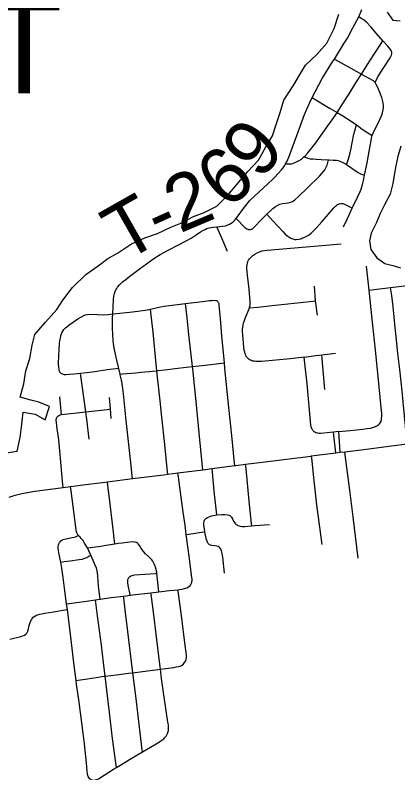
# Model space of a CAD drawing. Extents: x 0 to 34, y -5.4 to 22.
# Drawn here: x 2.686 to 3.075, y 18.856 to 19.626 of the extents above; entities that cross this region are included whole.
import ezdxf

# ---------------------------------------------------------------- set-up
doc = ezdxf.new("R2010")
doc.units = 0
for name, color, linetype in [('GM_X_Corporation_Text', 7, 'Continuous'), ('GM_X_Major_Lake', 7, 'Continuous'), ('GM_X_Major_River', 7, 'Continuous'), ('GM_X_State_Route', 7, 'Continuous'), ('GM_X_Township_Road', 7, 'Continuous'), ('GM_X_Township_Road_Text', 7, 'Continuous')]:
    doc.layers.add(name, color=color, linetype=linetype)

msp = doc.modelspace()

# ---------------------------------------------------------------- linework, layer by layer
at = {"layer": 'GM_X_Major_Lake'}
msp.add_lwpolyline([(2.67653, 19.18094), (2.68793, 19.18266), (2.69079, 19.19666), (2.69252, 19.2103), (2.69384, 19.22242), (2.70611, 19.22053), (2.71626, 19.21474), (2.72083, 19.22807), (2.70997, 19.23262), (2.7016, 19.23445), (2.69104, 19.23765), (2.69466, 19.25126), (2.69675, 19.26451), (2.70073, 19.27697), (2.70321, 19.2906), (2.70565, 19.30119), (2.71645, 19.31392), (2.72802, 19.32665), (2.73423, 19.33642), (2.7439, 19.34917), (2.75774, 19.36224), (2.77, 19.37116), (2.77997, 19.37859), (2.7899, 19.38413), (2.80406, 19.3934), (2.81742, 19.39964), (2.83038, 19.40399), (2.84412, 19.41061), (2.85403, 19.41463), (2.86702, 19.42126), (2.87769, 19.42527), (2.89067, 19.4319), (2.90184, 19.44311), (2.9111, 19.45397), (2.92228, 19.46708), (2.93307, 19.47868), (2.94009, 19.49147), (2.94709, 19.50313), (2.95066, 19.5137), (2.95503, 19.52692), (2.95863, 19.53938), (2.9691, 19.55516), (2.97456, 19.56494), (2.98078, 19.5751), (2.99231, 19.58592), (3.00234, 19.59753), (3.00976, 19.61222), (3.01453, 19.62695)], dxfattribs=at)
at = {"layer": 'GM_X_Major_River'}
for points in [[(3.06383, 19.62883), (3.06939, 19.62077), (3.07696, 19.62028)], [(3.07767, 19.49273), (3.07447, 19.48216), (3.07244, 19.4727), (3.07078, 19.46324), (3.06951, 19.45491), (3.06669, 19.44394), (3.06122, 19.43302), (3.05654, 19.42437), (3.05299, 19.41531), (3.04752, 19.40439), (3.04588, 19.39644), (3.04727, 19.38769), (3.0532, 19.37925), (3.06145, 19.37343), (3.06937, 19.3714), (3.07729, 19.36901)]]:
    msp.add_lwpolyline(points, dxfattribs=at)
at = {"layer": 'GM_X_State_Route'}
msp.add_lwpolyline([(2.67957, 19.13608), (2.6858, 19.13813), (2.69242, 19.13973), (2.70584, 19.14214), (2.72147, 19.14416), (2.73458, 19.14588), (2.74216, 19.14687), (2.75212, 19.14818), (2.77961, 19.15162), (2.80515, 19.15482), (2.83653, 19.15875), (2.84098, 19.15931), (2.85118, 19.16062), (2.87656, 19.16387), (2.88581, 19.16506), (2.90901, 19.16804), (2.90987, 19.16814), (2.91997, 19.16941), (2.93392, 19.17116), (2.98629, 19.17784), (2.98691, 19.17792), (3.01146, 19.18105), (3.01602, 19.18164), (3.02083, 19.18222), (3.03992, 19.18463), (3.06828, 19.18825), (3.08399, 19.19021)], dxfattribs=at)
at = {"layer": 'GM_X_Township_Road'}
for p, q in [((2.73292, 19.2199), (2.73107, 19.23797)), ((3.01146, 19.18105), (3.0091, 19.20211)), ((3.01602, 19.18164), (3.01449, 19.20265)), ((2.82378, 19.0389), (2.83189, 19.0398)), ((2.76734, 19.03165), (2.77203, 19.03232)), ((2.73884, 19.02188), (2.73812, 19.02761))]:
    msp.add_line(p, q, dxfattribs=at)
for points in [[(2.94838, 19.45993), (2.94976, 19.46121), (2.95316, 19.46492), (2.95632, 19.46857), (2.95796, 19.47067), (2.95936, 19.47266), (2.96062, 19.47474), (2.96204, 19.47758), (2.96459, 19.48331), (2.97703, 19.51768), (2.97994, 19.5249), (2.98223, 19.53034), (2.98505, 19.53725), (2.98745, 19.54216), (2.9908, 19.54868), (2.99785, 19.56151), (3.00831, 19.57846), (3.0101, 19.58132), (3.02015, 19.59737), (3.02336, 19.60271), (3.02898, 19.61296), (3.0349, 19.62432), (3.03806, 19.6317)], [(3.06854, 19.58675), (3.06855, 19.58742), (3.0685, 19.58827), (3.06832, 19.58916), (3.06793, 19.59011), (3.06724, 19.59115), (3.06436, 19.5945), (3.05947, 19.59998), (3.05273, 19.60752), (3.04705, 19.61412), (3.04261, 19.61872), (3.04025, 19.62075), (3.03749, 19.6227), (3.0349, 19.62432)], [(2.96062, 19.47474), (2.96252, 19.47469), (2.9647, 19.47474), (2.96683, 19.47497), (2.9685, 19.47543), (2.97155, 19.47682), (2.97422, 19.47824), (2.97657, 19.47974), (2.97923, 19.48187), (2.98035, 19.48287), (2.98322, 19.48585), (2.99023, 19.49466), (3.00181, 19.51095), (3.01139, 19.52442), (3.01302, 19.52705), (3.01937, 19.5373), (3.02501, 19.54605), (3.03196, 19.55727), (3.03761, 19.56598), (3.04628, 19.57937), (3.05755, 19.59698), (3.05947, 19.59998)], [(3.05168, 19.55737), (3.05251, 19.55957), (3.05405, 19.56266), (3.05586, 19.56581), (3.06626, 19.58139), (3.0676, 19.58383), (3.06818, 19.58525), (3.06854, 19.58675)], [(3.0101, 19.58132), (3.02669, 19.5721), (3.03761, 19.56598), (3.04079, 19.56419), (3.04942, 19.55937), (3.05065, 19.55847), (3.05168, 19.55737)], [(3.01932, 19.41068), (3.02333, 19.41926), (3.02826, 19.42982), (3.03349, 19.44085), (3.03632, 19.44683), (3.0373, 19.44914), (3.03819, 19.45154), (3.03918, 19.45507), (3.03978, 19.45775), (3.04086, 19.46333), (3.04355, 19.47596), (3.04488, 19.48364), (3.04752, 19.49855), (3.04796, 19.50103), (3.04862, 19.50363), (3.04945, 19.50608), (3.05061, 19.5084), (3.05434, 19.51561), (3.05807, 19.52378), (3.05903, 19.52675), (3.05974, 19.52977), (3.05999, 19.53215), (3.05993, 19.53415), (3.0596, 19.53698), (3.05909, 19.53948), (3.05819, 19.54219), (3.05413, 19.55236), (3.05271, 19.55545), (3.05168, 19.55737)], [(2.98745, 19.54216), (2.98967, 19.54081), (3.00587, 19.5312), (3.01302, 19.52705), (3.01886, 19.52368), (3.02714, 19.51835), (3.03253, 19.51444), (3.03449, 19.51301), (3.03693, 19.51125), (3.04151, 19.508), (3.04578, 19.50524), (3.04862, 19.50363)], [(3.02251, 19.47417), (3.02313, 19.476), (3.02452, 19.47992), (3.02525, 19.48215), (3.02627, 19.48602), (3.02683, 19.489), (3.02814, 19.49633), (3.03006, 19.50484), (3.03096, 19.50846), (3.03193, 19.51214), (3.03253, 19.51444)], [(2.94136, 19.42352), (2.94751, 19.4295), (2.95028, 19.43155), (2.95269, 19.43288), (2.9548, 19.43373), (2.95746, 19.43434), (2.96331, 19.4353), (2.96553, 19.43582), (2.96741, 19.43657), (2.96994, 19.43832), (2.97374, 19.44158), (2.98255, 19.44997), (2.99509, 19.46241), (2.99901, 19.46688), (3.0004, 19.46875), (3.00125, 19.47014), (3.00214, 19.472), (3.00277, 19.47355), (3.00352, 19.47624), (3.00413, 19.479)], [(2.97923, 19.48187), (2.98119, 19.48116), (2.98317, 19.48044), (2.98552, 19.47998), (2.98853, 19.4798), (2.99177, 19.47961), (2.99658, 19.47937), (3.00413, 19.479), (3.00488, 19.47896), (3.00886, 19.47872), (3.01064, 19.47872), (3.01243, 19.47858), (3.01389, 19.4783), (3.01563, 19.47769), (3.01931, 19.47591), (3.02251, 19.47417), (3.02776, 19.47053), (3.03432, 19.46598), (3.03682, 19.46457), (3.03884, 19.46382), (3.04086, 19.46333)], [(2.91047, 19.41932), (2.91876, 19.43086), (2.92398, 19.43712), (2.92924, 19.44247), (2.94219, 19.45418), (2.94838, 19.45993)], [(2.94136, 19.42352), (2.94746, 19.41691), (2.95759, 19.40599), (2.96029, 19.40349), (2.96271, 19.40147), (2.96579, 19.39938), (2.96808, 19.39843), (2.96952, 19.39804), (2.97121, 19.39784), (2.97405, 19.39814), (2.97589, 19.39867), (2.97723, 19.3992), (2.97999, 19.40036), (2.98264, 19.40162), (2.98442, 19.40265), (2.9865, 19.40442), (2.99181, 19.40987), (2.99731, 19.41581), (3.00389, 19.42346), (3.00971, 19.4302), (3.01122, 19.43174), (3.01214, 19.43261), (3.01334, 19.43355), (3.01434, 19.43398), (3.01547, 19.43431), (3.01673, 19.43452), (3.01859, 19.43439), (3.01989, 19.43403), (3.02094, 19.4336), (3.02584, 19.43107), (3.02826, 19.42982)], [(2.91047, 19.41932), (2.91913, 19.41007), (2.92017, 19.4093), (2.92122, 19.40874), (2.9221, 19.40841), (2.92301, 19.40823), (2.92394, 19.40816), (2.92486, 19.40824), (2.92585, 19.40852), (2.9266, 19.40884), (2.92761, 19.40949), (2.9286, 19.41031), (2.93658, 19.41858), (2.94136, 19.42352)], [(2.80515, 19.15482), (2.80484, 19.15739), (2.80318, 19.1714), (2.79863, 19.21392), (2.79596, 19.24119), (2.79494, 19.24904), (2.79379, 19.25507), (2.79253, 19.26045), (2.79238, 19.26108), (2.79105, 19.26677), (2.78908, 19.27517), (2.78737, 19.28287), (2.78616, 19.28953), (2.78542, 19.29537), (2.78496, 19.30137), (2.78476, 19.30827), (2.78478, 19.31811), (2.78495, 19.32222), (2.78524, 19.32929), (2.78572, 19.33698), (2.78614, 19.34022), (2.78663, 19.34295), (2.78736, 19.34496), (2.78814, 19.34672), (2.78893, 19.34813), (2.78981, 19.34939), (2.79179, 19.35184), (2.79484, 19.35476), (2.79809, 19.35742), (2.80237, 19.36079), (2.81175, 19.36761), (2.82668, 19.37848), (2.83299, 19.38256), (2.84191, 19.38734), (2.85122, 19.39203), (2.85968, 19.39642), (2.86472, 19.39934), (2.86977, 19.40275), (2.87403, 19.40562), (2.87652, 19.40714), (2.87872, 19.40823), (2.88066, 19.40908), (2.88291, 19.40976), (2.88693, 19.41043), (2.89073, 19.41084), (2.89666, 19.41147), (2.89946, 19.41195), (2.90184, 19.41275), (2.90356, 19.4136), (2.90525, 19.41455), (2.90717, 19.41575), (2.90877, 19.41732), (2.91047, 19.41932)], [(2.90149, 19.38586), (2.89944, 19.39061), (2.89604, 19.39851), (2.89211, 19.40762), (2.89073, 19.41084)], [(3.01449, 19.20265), (3.0091, 19.20211), (2.99609, 19.20089), (2.99463, 19.20088), (2.99343, 19.20101), (2.9925, 19.20119), (2.99143, 19.20154), (2.99023, 19.20212), (2.98958, 19.20257), (2.9887, 19.20332), (2.98809, 19.20406), (2.98763, 19.20481), (2.98706, 19.20588), (2.98665, 19.20743), (2.98631, 19.20919), (2.98238, 19.25127), (2.9804, 19.269), (2.97935, 19.27848), (2.96542, 19.27676), (2.93608, 19.27403), (2.93359, 19.27385), (2.93035, 19.27387), (2.92861, 19.27409), (2.92709, 19.27437), (2.92582, 19.27479), (2.92458, 19.27535), (2.92359, 19.27593), (2.92289, 19.27649), (2.92217, 19.27716), (2.92147, 19.27795), (2.92065, 19.27901), (2.92006, 19.28024), (2.91951, 19.28162), (2.91899, 19.28335), (2.91856, 19.28545), (2.91815, 19.2884), (2.91687, 19.30459), (2.9169, 19.30665), (2.91704, 19.30843), (2.91741, 19.31076), (2.91789, 19.31283), (2.91875, 19.31543), (2.91993, 19.3186), (2.92346, 19.32739), (2.92379, 19.32841), (2.92403, 19.32915), (2.92447, 19.33092), (2.92467, 19.33269), (2.92466, 19.33503), (2.92352, 19.34754), (2.92191, 19.36174), (2.92151, 19.36563), (2.92132, 19.36824), (2.92132, 19.37003), (2.92151, 19.3725), (2.92184, 19.37401), (2.92231, 19.37553), (2.92293, 19.37677), (2.92404, 19.37831), (2.92525, 19.37971), (2.92733, 19.38155), (2.92944, 19.38309), (2.93169, 19.38445), (2.93401, 19.38554), (2.93662, 19.3863), (2.9418, 19.38713), (2.99743, 19.39188), (3.01687, 19.39368)], [(3.01449, 19.20265), (3.02627, 19.20382), (3.03912, 19.20511), (3.04333, 19.20568), (3.04727, 19.2063), (3.04997, 19.20706), (3.05205, 19.20787), (3.05332, 19.20851), (3.0543, 19.20918), (3.05528, 19.21), (3.05596, 19.2107), (3.05673, 19.21167), (3.05719, 19.21257), (3.05762, 19.21366), (3.0579, 19.21473), (3.05812, 19.21619), (3.05823, 19.21758), (3.05821, 19.2209), (3.05778, 19.22706), (3.05564, 19.24829), (3.05213, 19.2823), (3.04854, 19.31702), (3.04549, 19.34634), (3.04282, 19.37092)], [(2.99283, 19.32095), (2.9911, 19.33548), (2.98984, 19.35046)], [(3.04549, 19.34634), (3.05041, 19.34695), (3.06731, 19.34905), (3.07819, 19.35038), (3.09072, 19.35179), (3.09471, 19.35212), (3.09605, 19.35207), (3.0975, 19.35191), (3.09846, 19.35172), (3.09948, 19.35131), (3.10025, 19.35087)], [(3.08399, 19.19021), (3.08364, 19.19409), (3.08077, 19.22573), (3.07914, 19.24367), (3.07812, 19.25333), (3.07679, 19.26592), (3.07473, 19.28202), (3.07307, 19.29926), (3.07199, 19.30802), (3.0697, 19.32982), (3.06839, 19.34086), (3.06731, 19.34905)], [(2.78495, 19.32222), (2.78862, 19.32261), (2.80204, 19.32404), (2.81089, 19.32499), (2.81509, 19.32558), (2.81806, 19.32609), (2.82321, 19.32722), (2.83357, 19.32949), (2.83722, 19.33014), (2.84273, 19.33095), (2.85901, 19.33285), (2.87872, 19.33533), (2.88309, 19.33581), (2.88604, 19.33606), (2.88795, 19.3361), (2.88943, 19.33599), (2.89035, 19.33579), (2.89113, 19.33543)], [(2.87656, 19.16387), (2.87627, 19.16676), (2.87274, 19.20157), (2.86969, 19.23326), (2.86621, 19.26657), (2.86598, 19.26872), (2.86273, 19.29837), (2.86023, 19.3215), (2.85901, 19.33285)], [(2.90901, 19.16804), (2.90875, 19.1706), (2.90586, 19.19876), (2.90306, 19.22722), (2.89892, 19.26679), (2.89842, 19.27241), (2.89594, 19.30016), (2.89447, 19.31777), (2.89311, 19.33125), (2.89292, 19.33246), (2.89275, 19.33306), (2.89255, 19.33356), (2.89213, 19.33433), (2.89165, 19.33497), (2.89113, 19.33543)], [(2.92379, 19.32841), (2.93251, 19.32929), (2.94675, 19.33073), (2.98519, 19.33485), (2.9911, 19.33548)], [(2.84098, 19.15931), (2.84071, 19.16179), (2.83778, 19.18958), (2.83483, 19.21733), (2.83313, 19.23399), (2.83181, 19.24604), (2.83052, 19.25784), (2.8297, 19.26453), (2.8293, 19.26774), (2.82588, 19.30364), (2.82393, 19.32087), (2.82321, 19.32722)], [(2.79105, 19.26677), (2.78847, 19.26644), (2.77928, 19.26527), (2.76688, 19.26355), (2.75877, 19.26245), (2.75227, 19.26183), (2.74551, 19.26119), (2.74108, 19.26083), (2.73725, 19.2605), (2.73595, 19.2605), (2.73487, 19.26067), (2.7341, 19.26091), (2.73318, 19.26131), (2.73238, 19.26185), (2.73173, 19.26247), (2.73129, 19.26312), (2.73094, 19.26398), (2.73061, 19.26493), (2.73036, 19.26603), (2.73003, 19.26831), (2.72985, 19.27123), (2.73008, 19.28013), (2.731, 19.29214), (2.7313, 19.29502), (2.73171, 19.29767), (2.73233, 19.30042), (2.73332, 19.3031), (2.73417, 19.3046), (2.73535, 19.30638), (2.73694, 19.30808), (2.7418, 19.31195), (2.74947, 19.31721), (2.75541, 19.32057), (2.75708, 19.32124), (2.75928, 19.32179), (2.76139, 19.32198), (2.76913, 19.32161), (2.77583, 19.32131), (2.78069, 19.32162), (2.78495, 19.32222)], [(2.97935, 19.27848), (2.99139, 19.28), (2.99732, 19.28067), (3.0111, 19.28222)], [(3.00059, 19.24548), (2.99771, 19.27648), (2.99732, 19.28067)], [(2.79238, 19.26108), (2.79442, 19.26126), (2.80388, 19.26209), (2.80816, 19.26248), (2.81349, 19.26296), (2.81752, 19.26332), (2.82213, 19.26377), (2.82533, 19.26407), (2.8297, 19.26453), (2.83076, 19.26465), (2.83792, 19.26549), (2.84846, 19.26672), (2.85943, 19.26798), (2.86598, 19.26872), (2.87893, 19.2702), (2.89842, 19.27241)], [(2.76109, 19.19506), (2.7587, 19.21545), (2.75769, 19.22276), (2.75634, 19.2325), (2.7526, 19.2595), (2.75227, 19.26183)], [(2.78347, 19.21606), (2.78261, 19.22564), (2.78158, 19.2373)], [(2.73458, 19.14588), (2.73434, 19.14859), (2.73134, 19.18297), (2.73006, 19.19435), (2.72815, 19.20808), (2.72767, 19.21218), (2.72751, 19.21393), (2.7276, 19.21496), (2.72777, 19.21591), (2.72795, 19.21646), (2.72829, 19.21708), (2.72859, 19.21759), (2.72921, 19.21828), (2.72989, 19.21879), (2.73082, 19.21931), (2.73164, 19.21958), (2.73292, 19.2199), (2.75769, 19.22276), (2.77928, 19.22526), (2.78261, 19.22564)], [(2.99787, 19.08798), (2.9923, 19.12819), (2.98918, 19.15575), (2.98742, 19.17301), (2.98691, 19.17792)], [(3.03416, 19.07394), (3.02913, 19.11593), (3.02589, 19.14303), (3.02125, 19.17898), (3.02083, 19.18222)], [(2.92625, 19.10682), (2.92602, 19.10911), (2.92371, 19.1321), (2.92043, 19.16485), (2.91997, 19.16941)], [(2.89061, 19.1179), (2.88814, 19.14221), (2.88618, 19.16144), (2.88581, 19.16506)], [(2.86318, 19.04568), (2.86387, 19.04648), (2.86433, 19.04721), (2.86472, 19.04807), (2.86516, 19.04926), (2.86538, 19.05021), (2.8655, 19.05119), (2.86547, 19.05265), (2.86538, 19.05419), (2.86511, 19.05685), (2.86258, 19.07592), (2.85966, 19.0981), (2.85842, 19.1074), (2.85664, 19.1207), (2.85177, 19.15636), (2.85118, 19.16062)], [(2.77203, 19.03232), (2.77061, 19.04538), (2.77012, 19.05095), (2.76971, 19.05561), (2.76929, 19.0593), (2.76876, 19.0624), (2.76827, 19.06403), (2.76721, 19.06662), (2.76611, 19.06926), (2.76264, 19.07699), (2.76062, 19.0815), (2.75915, 19.08462), (2.75636, 19.08936), (2.75445, 19.09239), (2.75299, 19.09415), (2.75169, 19.09547), (2.74986, 19.09712), (2.74905, 19.09827), (2.7483, 19.09988), (2.74803, 19.10084), (2.74767, 19.10283), (2.74526, 19.12133), (2.74268, 19.1425), (2.74216, 19.14687)], [(2.78704, 19.08861), (2.78637, 19.09413), (2.78527, 19.10336), (2.78155, 19.13472), (2.78005, 19.14775), (2.77961, 19.15162)], [(2.87858, 19.10077), (2.87806, 19.10397), (2.87764, 19.10753), (2.8776, 19.1097), (2.87786, 19.11165), (2.87812, 19.11258), (2.87866, 19.11342), (2.87963, 19.11431), (2.88109, 19.11524), (2.88287, 19.11604), (2.88543, 19.11688), (2.89061, 19.1179)], [(2.89061, 19.1179), (2.8958, 19.11826), (2.89894, 19.11826), (2.9016, 19.11804), (2.90315, 19.11769), (2.90397, 19.11734), (2.90465, 19.11685), (2.90576, 19.11565), (2.90665, 19.11414), (2.90776, 19.11173), (2.9086, 19.11021), (2.90926, 19.10932), (2.91033, 19.1083), (2.91121, 19.10773), (2.91219, 19.1072), (2.91339, 19.10671), (2.91441, 19.10649), (2.91644, 19.10627), (2.91905, 19.10632), (2.92625, 19.10682), (2.92947, 19.10709), (2.94429, 19.10827)], [(2.85966, 19.0981), (2.86222, 19.0985), (2.87501, 19.10028), (2.87858, 19.10077)], [(2.89839, 19.05876), (2.89669, 19.07508), (2.89612, 19.0787), (2.89542, 19.08152), (2.89479, 19.08325), (2.89419, 19.08411), (2.89366, 19.08464), (2.89309, 19.08518), (2.89197, 19.08587), (2.8907, 19.08634), (2.88874, 19.08667), (2.88549, 19.087), (2.88426, 19.08726), (2.88336, 19.08766), (2.8826, 19.08823), (2.88203, 19.08885), (2.8812, 19.09041), (2.88054, 19.09211), (2.87997, 19.09394), (2.8795, 19.09573), (2.87858, 19.10077)], [(2.73812, 19.02761), (2.73639, 19.04085), (2.73461, 19.05428), (2.73305, 19.0639), (2.73204, 19.07007), (2.73055, 19.07774), (2.72984, 19.08168), (2.72956, 19.08461), (2.72964, 19.08622), (2.72984, 19.08743), (2.73016, 19.08854), (2.73052, 19.08931), (2.73092, 19.09003), (2.73136, 19.09063), (2.73228, 19.0916), (2.7332, 19.09228), (2.73449, 19.09301), (2.73578, 19.09348), (2.7438, 19.09489), (2.74616, 19.09547), (2.74763, 19.09604), (2.74986, 19.09712)], [(2.75915, 19.08462), (2.77282, 19.08629), (2.77635, 19.08675), (2.78021, 19.08743), (2.78704, 19.08861), (2.7906, 19.08912), (2.79443, 19.08971), (2.79971, 19.09043), (2.80244, 19.09073), (2.8051, 19.09085), (2.80723, 19.09071), (2.80838, 19.09041), (2.8091, 19.09009)], [(2.83189, 19.0398), (2.83154, 19.04277), (2.8297, 19.05861), (2.82958, 19.05966), (2.82853, 19.06489), (2.82748, 19.06762), (2.82643, 19.06964), (2.82554, 19.07103), (2.82455, 19.07234), (2.82297, 19.07397), (2.82126, 19.07558), (2.8183, 19.07852), (2.8161, 19.08083), (2.81511, 19.08203), (2.81349, 19.08442), (2.81207, 19.08679), (2.81086, 19.08847), (2.81038, 19.08915), (2.80982, 19.08968), (2.8091, 19.09009)], [(2.73204, 19.07007), (2.73543, 19.07059), (2.74166, 19.07144), (2.75087, 19.07259), (2.7538, 19.07313), (2.75662, 19.07402), (2.75869, 19.07484), (2.76075, 19.07597), (2.76264, 19.07699)], [(2.8026, 19.03642), (2.80218, 19.03862), (2.80073, 19.04619), (2.80021, 19.04924), (2.80011, 19.05051), (2.80014, 19.05154), (2.80029, 19.05241), (2.80054, 19.05307), (2.80088, 19.05382), (2.80129, 19.0545), (2.80197, 19.05509), (2.80296, 19.05572), (2.80373, 19.05613), (2.80469, 19.05645), (2.80577, 19.05672), (2.80704, 19.0569), (2.82801, 19.05848), (2.8297, 19.05861)], [(2.77203, 19.03232), (2.78347, 19.03386), (2.79585, 19.03552), (2.8026, 19.03642), (2.80794, 19.03713), (2.82378, 19.0389)], [(2.83913, 18.89324), (2.84063, 18.89566), (2.84107, 18.89675), (2.84151, 18.89873), (2.84175, 18.90118), (2.8415, 18.90454), (2.84106, 18.90729), (2.83966, 18.91644), (2.83687, 18.93518), (2.83451, 18.95176), (2.83339, 18.96111), (2.83279, 18.96614), (2.82904, 18.99666), (2.82662, 19.01642), (2.82397, 19.03739), (2.82378, 19.0389)], [(2.83189, 19.0398), (2.84263, 19.04103), (2.85124, 19.04196), (2.8525, 19.0421), (2.85564, 19.0426), (2.85799, 19.04313), (2.86035, 19.0439), (2.86198, 19.04477), (2.86318, 19.04568)], [(2.858, 18.96786), (2.85894, 18.96941), (2.85957, 18.97109), (2.85989, 18.97329), (2.85978, 18.97571), (2.85925, 18.98033), (2.85862, 18.98537), (2.85471, 19.01586), (2.85145, 19.04041), (2.85124, 19.04196)], [(2.73812, 19.02761), (2.75578, 19.03008), (2.76734, 19.03165)], [(2.7888, 18.86124), (2.78815, 18.86601), (2.78482, 18.89058), (2.78164, 18.91697), (2.77721, 18.9542), (2.77555, 18.9681), (2.7735, 18.98554), (2.76955, 19.01552), (2.76734, 19.03165)], [(2.81521, 18.87705), (2.81494, 18.87917), (2.81207, 18.90209), (2.80835, 18.93418), (2.80547, 18.95762), (2.80034, 18.99961), (2.79763, 19.02145), (2.79609, 19.03364), (2.79585, 19.03552)], [(2.68044, 18.99155), (2.6914, 18.9943), (2.6937, 18.99496), (2.69524, 18.99562), (2.69677, 18.99661), (2.69765, 18.99781), (2.69852, 18.99968), (2.69885, 19.00099), (2.69997, 19.00551), (2.70136, 19.00949), (2.70268, 19.01207), (2.7041, 19.01393), (2.70564, 19.01514), (2.70761, 19.01612), (2.71078, 19.017), (2.71594, 19.01799), (2.7246, 19.01942), (2.73665, 19.0215), (2.73884, 19.02188)], [(2.76285, 18.84881), (2.76192, 18.84934), (2.7612, 18.84998), (2.76052, 18.85102), (2.76004, 18.85214), (2.75967, 18.85323), (2.75928, 18.85479), (2.75903, 18.85684), (2.75852, 18.86184), (2.75762, 18.87251), (2.75609, 18.88524), (2.75475, 18.8961), (2.75076, 18.92767), (2.74826, 18.94601), (2.74779, 18.94967), (2.74579, 18.96505), (2.74241, 18.99365), (2.73884, 19.02188)], [(2.74779, 18.94967), (2.74982, 18.94999), (2.75945, 18.95149), (2.76813, 18.95286), (2.77597, 18.95402), (2.77721, 18.9542), (2.78879, 18.9555), (2.80099, 18.95706), (2.80547, 18.95762), (2.81513, 18.95882), (2.83339, 18.96111), (2.83605, 18.96144), (2.84708, 18.96303), (2.84939, 18.96341), (2.8517, 18.96384), (2.85328, 18.96426), (2.85485, 18.96499), (2.85633, 18.96603), (2.858, 18.96786)], [(2.76285, 18.84881), (2.76381, 18.84853), (2.76514, 18.84842), (2.7663, 18.84842), (2.76758, 18.84861), (2.76879, 18.84902), (2.77052, 18.84982), (2.77613, 18.85336), (2.78575, 18.85939), (2.7888, 18.86124), (2.80381, 18.87033), (2.81521, 18.87705), (2.8274, 18.88425), (2.83247, 18.8874), (2.83487, 18.889), (2.83675, 18.8905), (2.838, 18.89187), (2.83913, 18.89324)]]:
    msp.add_lwpolyline(points, dxfattribs=at)

# ---------------------------------------------------------------- texts
at = {"layer": 'GM_X_Corporation_Text'}
msp.add_text('POINT', height=0.094697, rotation=0.00001, dxfattribs=at).set_placement((2.34671, 19.54656))
at = {"layer": 'GM_X_Township_Road_Text'}
for s, rotation, p in [('9', 49.95004, (2.93473, 19.45706)), ('6', 40.20276, (2.90078, 19.4272)), ('2', 22.91256, (2.85292, 19.40393)), ('T', 29.56993, (2.7965, 19.3743)), ('-', 24.16575, (2.83213, 19.3946))]:
    msp.add_text(s, height=0.05682, rotation=rotation, dxfattribs=at).set_placement(p)

doc.saveas('drawing.dxf')
